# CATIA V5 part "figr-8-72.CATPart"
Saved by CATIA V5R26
Part number: Part1
Bounding box of the stored display mesh (mm): x -81.893 to 81.893, y -175.508 to 175.508, z -50 to 146
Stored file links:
  D:\_Deepak\CATIA\CATIA V5-6R2016_Deepak\Resources\Part files\Partfiles\c08_catia_v5_6r2016_prt\figr-8-72.CATPart
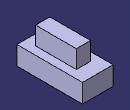
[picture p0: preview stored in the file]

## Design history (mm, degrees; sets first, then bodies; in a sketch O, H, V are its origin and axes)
Body1 (main body)
  Sketch1 on xy-plane, origin (0, 0, 0), H (1, 0, 0), V (0, 1, 0)
    line L1 (-81.8929, 175.5076) -> (81.8929, 175.5076)
    line L2 (81.8929, 175.5076) -> (81.8929, -175.5076)
    line L3 (81.8929, -175.5076) -> (-81.8929, -175.5076)
    line L4 (-81.8929, -175.5076) -> (-81.8929, 175.5076)
    axis line L5 (81.8929, -175.5076) -> (-81.8929, 175.5076)
    horizontal: L1 H, L3 H
    vertical: L2 V, L4 V
    midpoint: O L5
  Pad1: profile Sketch1, direction (0, 0, 1), length 50, mirrored extent
  Body2
    Sketch2 on xy-plane, origin (0, 0, 0), H (1, 0, 0), V (0, 1, 0)
      line L1 (-37.4906, 99.3013) -> (38.4681, 99.3013)
      line L2 (38.4681, 99.3013) -> (38.4681, -118.5305)
      line L3 (38.4681, -118.5305) -> (-37.4906, -118.5305)
      line L4 (-37.4906, -118.5305) -> (-37.4906, 99.3013)
      horizontal: L1 H, L3 H
      vertical: L2 V, L4 V
    Pad2: profile Sketch2, direction (0, 0, 1), length 146, opposite side length 150
  Trim1: tool Body2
